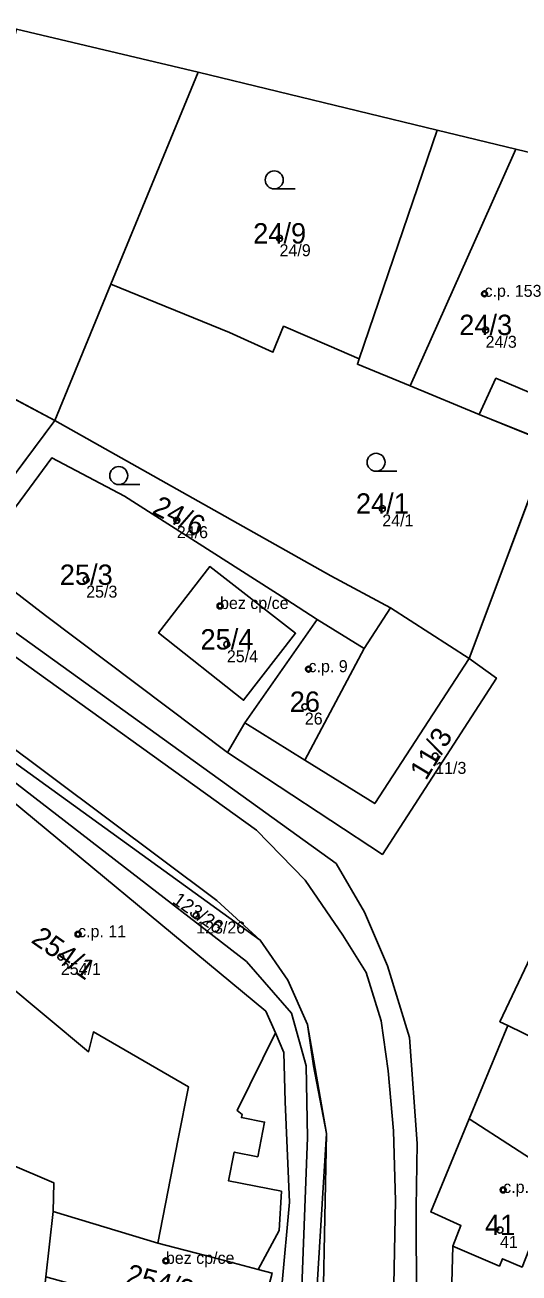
# Model space of a CAD drawing. Extents: x -603967 to -594699, y -1179315 to -1165625.
# Drawn here: x -597461.9 to -597420.7, y -1172597.8 to -1172493.5 of the extents above; entities that cross this region are included whole.
import ezdxf

# ---------------------------------------------------------------- set-up
doc = ezdxf.new("R2010")
doc.units = 0
for name, color, linetype in [('Definiční body', 7, 'Continuous'), ('Hranice parcel', 7, 'Continuous'), ('Parcelní čísla', 7, 'Continuous'), ('Polygon budovy', 7, 'Continuous'), ('Polygon parcely', 7, 'Continuous'), ('Vnitřní kresba', 7, 'Continuous'), ('Značky budov', 7, 'Continuous'), ('Značky kultur', 7, 'Continuous')]:
    doc.layers.add(name, color=color, linetype=linetype)

msp = doc.modelspace()

# ---------------------------------------------------------------- linework, layer by layer
at = {"layer": 'Definiční body'}
for centre in [(-597440.66, -1172511.29994), (-597423.54, -1172515.92994), (-597423.45, -1172518.94994), (-597432.08, -1172533.87994), (-597449.24, -1172534.85994), (-597456.81, -1172539.82994), (-597445.63, -1172542.01994), (-597445.06, -1172545.22994), (-597438.24, -1172547.29994), (-597438.55, -1172550.43994), (-597427.66, -1172554.55994), (-597447.62, -1172567.89994), (-597457.49, -1172569.44994), (-597458.93, -1172571.35994), (-597421.98, -1172590.81994), (-597422.25, -1172594.16994), (-597450.15, -1172596.74994)]:
    msp.add_circle(centre, 0.25, dxfattribs=at)
at = {"layer": 'Hranice parcel'}
for p, q in [((-597462.64, -1172493.8), (-597447.46, -1172497.41)), ((-597454.74, -1172515.13), (-597447.46, -1172497.41)), ((-597447.46, -1172497.41), (-597427.5, -1172502.26)), ((-597427.5, -1172502.26), (-597434.01, -1172521.36)), ((-597459.42, -1172526.51), (-597480.25, -1172515.46)), ((-597454.74, -1172515.13), (-597459.42, -1172526.51)), ((-597423.99, -1172526.01), (-597429.76, -1172523.62)), ((-597418.08, -1172528.4), (-597423.99, -1172526.01)), ((-597467.38, -1172537.18), (-597459.42, -1172526.51)), ((-597418.08, -1172528.4), (-597424.82, -1172546.4)), ((-597431.39, -1172542.18), (-597424.82, -1172546.4)), ((-597437.51, -1172543.14), (-597443.55, -1172551.79)), ((-597443.55, -1172551.79), (-597445.01, -1172554.25)), ((-597424.81, -1172584.87), (-597421.59, -1172577.08)), ((-597460.17, -1172598.07), (-597459.57, -1172592.62))]:
    msp.add_line(p, q, dxfattribs=at)
for points in [[(-597528.05, -1172498.17), (-597518.4, -1172504.13), (-597435.94, -1172563.53), (-597433.57, -1172567.6), (-597431.64, -1172572.1), (-597429.8, -1172578.09), (-597429.17, -1172586.93), (-597429.24, -1172592.29), (-597429.03, -1172657.03)], [(-597427.5, -1172502.26), (-597420.93, -1172503.84), (-597418.29, -1172504.48), (-597418.2, -1172505.62), (-597411.97, -1172507.07), (-597410.25, -1172507.47)], [(-597434.01, -1172521.36), (-597436.52, -1172520.28), (-597440.33, -1172518.64), (-597441.21, -1172520.81), (-597444.84, -1172519.15), (-597454.74, -1172515.13)], [(-597429.76, -1172523.62), (-597434.16, -1172521.81), (-597434.01, -1172521.36)], [(-597459.42, -1172526.51), (-597436.37, -1172539.5), (-597431.39, -1172542.18)], [(-597466.09, -1172538.29), (-597459.67, -1172529.63), (-597453.61, -1172532.84), (-597440.13, -1172541.45), (-597437.51, -1172543.14)], [(-597495.52, -1172531.46), (-597442.28, -1172569.94), (-597439.98, -1172573.3), (-597438.33, -1172576.99), (-597436.73, -1172586.11), (-597440.82, -1172652.61)], [(-597440.82, -1172652.61), (-597438.34, -1172586.43), (-597438.45, -1172580.46), (-597439.65, -1172576.06), (-597443.41, -1172571.74), (-597495.52, -1172531.46)], [(-597445.01, -1172554.25), (-597460.2, -1172542.81), (-597466.09, -1172538.29)], [(-597439.32, -1172544.3), (-597443.66, -1172549.9), (-597450.77, -1172544.27), (-597446.49, -1172538.73), (-597439.32, -1172544.3)], [(-597431.39, -1172542.18), (-597433.6, -1172545.57), (-597437.51, -1172543.14)], [(-597424.82, -1172546.4), (-597422.55, -1172548.04), (-597432.07, -1172562.78), (-597445.01, -1172554.25)], [(-597424.82, -1172546.4), (-597432.71, -1172558.53), (-597438.56, -1172554.9), (-597443.55, -1172551.79)], [(-597466.04, -1172555.82), (-597441.8, -1172575.89), (-597441.01, -1172577.69), (-597440.3, -1172579.33), (-597440.2, -1172583.46), (-597439.84, -1172591.85), (-597440.47, -1172598.85), (-597441.4, -1172612.41)], [(-597421.59, -1172577.08), (-597422.26, -1172576.76), (-597418.4, -1172568.61)], [(-597421.59, -1172577.08), (-597415.23, -1172580.2), (-597406.14, -1172584.66), (-597403.06, -1172585.98)], [(-597459.57, -1172592.62), (-597459.5, -1172590.23), (-597471.27, -1172585.2), (-597477.85, -1172582.21), (-597477.75, -1172581.98)], [(-597426.39, -1172602.61), (-597426.19, -1172595.53), (-597425.51, -1172593.78), (-597428.03, -1172592.65), (-597424.81, -1172584.87)], [(-597424.81, -1172584.87), (-597417.43, -1172589.67), (-597409.1, -1172592.88)], [(-597459.57, -1172592.62), (-597450.82, -1172595.27), (-597446.2, -1172596.48), (-597442.45, -1172597.46), (-597441.27, -1172597.77), (-597442.65, -1172602.95), (-597446.75, -1172601.81)]]:
    msp.add_lwpolyline(points, dxfattribs=at)
at = {"layer": 'Polygon budovy'}
for points in [[(-597423.8, -1172510.28), (-597429.76, -1172523.62), (-597423.99, -1172526.01), (-597422.59, -1172522.98), (-597418.73, -1172524.62), (-597414.3, -1172514.46), (-597415.05, -1172514.13), (-597411.97, -1172507.07), (-597418.2, -1172505.62), (-597418.29, -1172504.48), (-597420.93, -1172503.84)], [(-597486.02, -1172522.96), (-597467.38, -1172537.18), (-597459.42, -1172526.51), (-597480.25, -1172515.46)], [(-597446.49, -1172538.73), (-597450.77, -1172544.27), (-597443.66, -1172549.9), (-597439.32, -1172544.3)], [(-597443.55, -1172551.79), (-597438.56, -1172554.9), (-597433.6, -1172545.57), (-597437.51, -1172543.14)], [(-597422.26, -1172576.76), (-597421.59, -1172577.08), (-597415.23, -1172580.2), (-597413.06, -1172575.4), (-597403, -1172579.74), (-597402.94, -1172579.58), (-597399.56, -1172581.07), (-597397.55, -1172578.25), (-597401.34, -1172576.5), (-597411.7, -1172571.55), (-597418.4, -1172568.61)], [(-597403.06, -1172585.98), (-597406.14, -1172584.66), (-597415.23, -1172580.2), (-597421.59, -1172577.08), (-597424.81, -1172584.87), (-597417.43, -1172589.67), (-597416.34, -1172586.92), (-597408.17, -1172590.65), (-597408.35, -1172591.04), (-597407.37, -1172591.49), (-597407.03, -1172590.74), (-597406.53, -1172590.97), (-597404.86, -1172587.32), (-597403.82, -1172587.79)], [(-597428.03, -1172592.65), (-597425.51, -1172593.78), (-597426.19, -1172595.53), (-597422.3, -1172597.19), (-597422.03, -1172596.57), (-597420.41, -1172597.27), (-597417.43, -1172589.67), (-597424.81, -1172584.87)], [(-597460.17, -1172598.07), (-597446.75, -1172601.81), (-597442.65, -1172602.95), (-597441.27, -1172597.77), (-597442.45, -1172597.46), (-597446.2, -1172596.48), (-597450.82, -1172595.27), (-597459.57, -1172592.62)]]:
    msp.add_lwpolyline(points, close=True, dxfattribs=at)
msp.add_lwpolyline([(-597463.68, -1172573.37), (-597456.61, -1172579.27), (-597456.2, -1172577.62), (-597448.27, -1172582.19), (-597449.12, -1172586.55), (-597450.82, -1172595.27), (-597446.2, -1172596.48), (-597442.45, -1172597.46), (-597440.7, -1172594.22), (-597440.5, -1172590.93), (-597444.92, -1172590.06), (-597444.44, -1172587.66), (-597442.48, -1172588.04), (-597441.91, -1172585.15), (-597443.84, -1172584.77), (-597443.79, -1172584.51), (-597444.21, -1172584.18), (-597441.01, -1172577.69), (-597441.8, -1172575.89), (-597466.04, -1172555.82)], dxfattribs=at)
at = {"layer": 'Polygon parcely'}
for points in [[(-597429.92, -1172665.33), (-597429.03, -1172657.03), (-597429.24, -1172592.29), (-597429.17, -1172586.93), (-597429.8, -1172578.09), (-597431.64, -1172572.1), (-597433.57, -1172567.6), (-597435.94, -1172563.53), (-597518.4, -1172504.13), (-597528.05, -1172498.17), (-597529.32, -1172493.99), (-597512.01, -1172395.8), (-597507.16, -1172367.89)], [(-597418.08, -1172528.4), (-597424.82, -1172546.4), (-597422.55, -1172548.04), (-597432.07, -1172562.78), (-597445.01, -1172554.25), (-597460.2, -1172542.81), (-597466.09, -1172538.29), (-597467.38, -1172537.18), (-597486.02, -1172522.96), (-597490.89, -1172519.38), (-597505.52, -1172508.34), (-597509.97, -1172505.92), (-597516.24, -1172503.23), (-597517.21, -1172502.81), (-597528.05, -1172498.17), (-597518.4, -1172504.13), (-597435.94, -1172563.53), (-597433.57, -1172567.6), (-597431.64, -1172572.1), (-597429.8, -1172578.09), (-597429.17, -1172586.93), (-597429.24, -1172592.29), (-597429.03, -1172657.03)], [(-597532.25, -1172503.88), (-597520.62, -1172513.32), (-597509.01, -1172523.4), (-597500.85, -1172530.35), (-597481.89, -1172547.09), (-597477.95, -1172549.3), (-597473.88, -1172551.53), (-597466.04, -1172555.82), (-597441.8, -1172575.89), (-597441.01, -1172577.69), (-597440.3, -1172579.33), (-597440.2, -1172583.46), (-597439.84, -1172591.85), (-597440.47, -1172598.85), (-597441.4, -1172612.41), (-597444.15, -1172652.28), (-597440.82, -1172652.61), (-597438.34, -1172586.43), (-597438.45, -1172580.46), (-597439.65, -1172576.06), (-597443.41, -1172571.74), (-597495.52, -1172531.46), (-597528.77, -1172505.76)], [(-597528.77, -1172505.76), (-597495.52, -1172531.46), (-597442.28, -1172569.94), (-597439.98, -1172573.3), (-597438.33, -1172576.99), (-597436.73, -1172586.11), (-597440.82, -1172652.61), (-597440.93, -1172655.49), (-597441.21, -1172665.3)], [(-597426.39, -1172602.61), (-597426.19, -1172595.53), (-597425.51, -1172593.78), (-597428.03, -1172592.65), (-597424.81, -1172584.87), (-597421.59, -1172577.08), (-597422.26, -1172576.76), (-597418.4, -1172568.61)]]:
    msp.add_lwpolyline(points, dxfattribs=at)
for points in [[(-597447.46, -1172497.41), (-597427.5, -1172502.26), (-597420.93, -1172503.84), (-597418.29, -1172504.48), (-597418.2, -1172505.62), (-597411.97, -1172507.07), (-597410.25, -1172507.47), (-597408.98, -1172507.8), (-597408.65, -1172507.01), (-597400.52, -1172485.2), (-597420.52, -1172482.15), (-597454.45, -1172476.98), (-597470.37, -1172474.54), (-597472.64, -1172490.37), (-597472.89, -1172491.36), (-597466.39, -1172492.92), (-597462.64, -1172493.8)], [(-597447.46, -1172497.41), (-597462.64, -1172493.8), (-597464.36, -1172500.36), (-597468.08, -1172499.46), (-597472.04, -1172498.55), (-597473.11, -1172503.48), (-597477.19, -1172502.57), (-597482.51, -1172517.86), (-597486.02, -1172522.96), (-597480.25, -1172515.46), (-597459.42, -1172526.51), (-597454.74, -1172515.13)], [(-597427.5, -1172502.26), (-597447.46, -1172497.41), (-597454.74, -1172515.13), (-597444.84, -1172519.15), (-597441.21, -1172520.81), (-597440.33, -1172518.64), (-597436.52, -1172520.28), (-597434.01, -1172521.36)], [(-597427.5, -1172502.26), (-597434.01, -1172521.36), (-597434.16, -1172521.81), (-597429.76, -1172523.62), (-597423.99, -1172526.01), (-597418.08, -1172528.4), (-597410.25, -1172507.47), (-597411.97, -1172507.07), (-597418.2, -1172505.62), (-597418.29, -1172504.48), (-597420.93, -1172503.84)], [(-597459.42, -1172526.51), (-597480.25, -1172515.46), (-597486.02, -1172522.96), (-597467.38, -1172537.18)], [(-597454.74, -1172515.13), (-597459.42, -1172526.51), (-597436.37, -1172539.5), (-597431.39, -1172542.18), (-597424.82, -1172546.4), (-597418.08, -1172528.4), (-597423.99, -1172526.01), (-597429.76, -1172523.62), (-597434.16, -1172521.81), (-597434.01, -1172521.36), (-597436.52, -1172520.28), (-597440.33, -1172518.64), (-597441.21, -1172520.81), (-597444.84, -1172519.15)], [(-597440.13, -1172541.45), (-597437.51, -1172543.14), (-597433.6, -1172545.57), (-597431.39, -1172542.18), (-597436.37, -1172539.5), (-597459.42, -1172526.51), (-597467.38, -1172537.18), (-597466.09, -1172538.29), (-597459.67, -1172529.63), (-597453.61, -1172532.84)], [(-597466.09, -1172538.29), (-597460.2, -1172542.81), (-597445.01, -1172554.25), (-597443.55, -1172551.79), (-597437.51, -1172543.14), (-597440.13, -1172541.45), (-597453.61, -1172532.84), (-597459.67, -1172529.63)], [(-597495.52, -1172531.46), (-597443.41, -1172571.74), (-597439.65, -1172576.06), (-597438.45, -1172580.46), (-597438.34, -1172586.43), (-597440.82, -1172652.61), (-597436.73, -1172586.11), (-597438.33, -1172576.99), (-597439.98, -1172573.3), (-597442.28, -1172569.94)], [(-597439.32, -1172544.3), (-597446.49, -1172538.73), (-597450.77, -1172544.27), (-597443.66, -1172549.9)], [(-597439.32, -1172544.3), (-597443.66, -1172549.9), (-597450.77, -1172544.27), (-597446.49, -1172538.73)], [(-597437.51, -1172543.14), (-597443.55, -1172551.79), (-597438.56, -1172554.9), (-597432.71, -1172558.53), (-597424.82, -1172546.4), (-597431.39, -1172542.18), (-597433.6, -1172545.57)], [(-597443.55, -1172551.79), (-597445.01, -1172554.25), (-597432.07, -1172562.78), (-597422.55, -1172548.04), (-597424.82, -1172546.4), (-597432.71, -1172558.53), (-597438.56, -1172554.9)], [(-597441.27, -1172597.77), (-597442.65, -1172602.95), (-597446.75, -1172601.81), (-597446.09, -1172609.08), (-597441.4, -1172612.41), (-597440.47, -1172598.85), (-597439.84, -1172591.85), (-597440.2, -1172583.46), (-597440.3, -1172579.33), (-597441.01, -1172577.69), (-597441.8, -1172575.89), (-597466.04, -1172555.82), (-597469.1, -1172564.5), (-597475.64, -1172577.53), (-597477.75, -1172581.98), (-597477.85, -1172582.21), (-597471.27, -1172585.2), (-597459.5, -1172590.23), (-597459.57, -1172592.62), (-597450.82, -1172595.27), (-597446.2, -1172596.48), (-597442.45, -1172597.46)], [(-597397.55, -1172578.25), (-597401.34, -1172576.5), (-597411.7, -1172571.55), (-597418.4, -1172568.61), (-597422.26, -1172576.76), (-597421.59, -1172577.08), (-597415.23, -1172580.2), (-597406.14, -1172584.66), (-597403.06, -1172585.98), (-597399.56, -1172581.07)], [(-597493.46, -1172568.87), (-597495.24, -1172572.96), (-597501.89, -1172569.57), (-597496.27, -1172582.09), (-597487.15, -1172599.91), (-597483.7, -1172612.09), (-597484.51, -1172631.8), (-597484.61, -1172633.77), (-597470.17, -1172634.48), (-597468.95, -1172626.48), (-597463.35, -1172626.75), (-597463.23, -1172625.41), (-597460.17, -1172598.07), (-597459.57, -1172592.62), (-597459.5, -1172590.23), (-597471.27, -1172585.2), (-597477.85, -1172582.21), (-597477.75, -1172581.98), (-597485.47, -1172578.76), (-597487.24, -1172576.43), (-597490.24, -1172573.31)], [(-597408.54, -1172593.09), (-597403.51, -1172594.53), (-597403.82, -1172587.79), (-597403.06, -1172585.98), (-597406.14, -1172584.66), (-597415.23, -1172580.2), (-597421.59, -1172577.08), (-597424.81, -1172584.87), (-597417.43, -1172589.67), (-597409.1, -1172592.88)], [(-597412.9, -1172602.8), (-597411.99, -1172602.78), (-597408.57, -1172602.69), (-597407.97, -1172602.77), (-597404.91, -1172596.01), (-597409.72, -1172594.41), (-597409.1, -1172592.88), (-597417.43, -1172589.67), (-597424.81, -1172584.87), (-597428.03, -1172592.65), (-597425.51, -1172593.78), (-597426.19, -1172595.53), (-597426.39, -1172602.61), (-597422.52, -1172602.67), (-597418.51, -1172602.73)], [(-597459.57, -1172592.62), (-597460.17, -1172598.07), (-597446.75, -1172601.81), (-597442.65, -1172602.95), (-597441.27, -1172597.77), (-597442.45, -1172597.46), (-597446.2, -1172596.48), (-597450.82, -1172595.27)]]:
    msp.add_lwpolyline(points, close=True, dxfattribs=at)
at = {"layer": 'Vnitřní kresba'}
for p, q in [((-597525.44, -1172501.23), (-597442.58, -1172560.76)), ((-597423.8, -1172510.28), (-597420.93, -1172503.84)), ((-597527.79, -1172505.43), (-597445.89, -1172566.62)), ((-597429.76, -1172523.62), (-597423.8, -1172510.28)), ((-597422.59, -1172522.98), (-597423.99, -1172526.01)), ((-597418.73, -1172524.62), (-597422.59, -1172522.98)), ((-597438.56, -1172554.9), (-597433.6, -1172545.57)), ((-597442.58, -1172560.76), (-597438.52, -1172564.92)), ((-597438.52, -1172564.92), (-597435.37, -1172569.52)), ((-597445.89, -1172566.62), (-597442.28, -1172569.94)), ((-597435.37, -1172569.52), (-597433.42, -1172572.66)), ((-597433.42, -1172572.66), (-597432.17, -1172576.69)), ((-597463.68, -1172573.37), (-597456.61, -1172579.27)), ((-597438.33, -1172576.99), (-597437.82, -1172580.44)), ((-597432.17, -1172576.69), (-597431.58, -1172580.88)), ((-597456.61, -1172579.27), (-597456.2, -1172577.62)), ((-597456.2, -1172577.62), (-597448.27, -1172582.19)), ((-597444.21, -1172584.18), (-597441.01, -1172577.69)), ((-597437.82, -1172580.44), (-597436.73, -1172586.11)), ((-597431.58, -1172580.88), (-597431.15, -1172585.88)), ((-597448.27, -1172582.19), (-597449.12, -1172586.55)), ((-597443.79, -1172584.51), (-597444.21, -1172584.18)), ((-597443.79, -1172584.51), (-597443.84, -1172584.77)), ((-597443.84, -1172584.77), (-597441.91, -1172585.15)), ((-597441.91, -1172585.15), (-597442.48, -1172588.04)), ((-597449.12, -1172586.55), (-597450.82, -1172595.27)), ((-597438.15, -1172655.85), (-597436.73, -1172586.11)), ((-597431.15, -1172585.88), (-597430.97, -1172591.72)), ((-597444.44, -1172587.66), (-597444.92, -1172590.06)), ((-597442.48, -1172588.04), (-597444.44, -1172587.66)), ((-597444.92, -1172590.06), (-597440.5, -1172590.93)), ((-597440.5, -1172590.93), (-597440.7, -1172594.22)), ((-597430.97, -1172591.72), (-597432.3, -1172656.61)), ((-597442.45, -1172597.46), (-597440.7, -1172594.22)), ((-597426.19, -1172595.53), (-597422.3, -1172597.19)), ((-597422.3, -1172597.19), (-597422.03, -1172596.57)), ((-597422.03, -1172596.57), (-597420.41, -1172597.27))]:
    msp.add_line(p, q, dxfattribs=at)
at = {"layer": 'Značky budov'}
for centre in [(-597423.5468, -1172515.92916), (-597445.6368, -1172542.01916), (-597438.2468, -1172547.29916), (-597457.4968, -1172569.44916), (-597421.9868, -1172590.81916), (-597450.1568, -1172596.74916)]:
    msp.add_circle(centre, 0.175, dxfattribs=at)
at = {"layer": 'Značky kultur'}
for p, q in [((-597441.103, -1172507.16), (-597439.353, -1172507.16)), ((-597432.603, -1172530.76), (-597430.853, -1172530.76)), ((-597454.093, -1172531.87), (-597452.343, -1172531.87))]:
    msp.add_line(p, q, dxfattribs=at)
for centre in [(-597441.10286, -1172506.40981), (-597432.60286, -1172530.00981), (-597454.09286, -1172531.11981)]:
    msp.add_circle(centre, 0.75, dxfattribs=at)

# ---------------------------------------------------------------- texts
at = {"layer": 'Definiční body'}
for s, p in [('24/9', (-597440.66, -1172512.789)), ('c.p. 153', (-597423.54, -1172516.18)), ('24/3', (-597423.45, -1172520.439)), ('24/1', (-597432.08, -1172535.369)), ('24/6', (-597449.24, -1172536.349)), ('25/3', (-597456.81, -1172541.319)), ('bez cp/ce', (-597445.63, -1172542.27)), ('25/4', (-597445.06, -1172546.719)), ('c.p. 9', (-597438.24, -1172547.55)), ('26', (-597438.55, -1172551.929)), ('11/3', (-597427.66, -1172556.049)), ('c.p. 11', (-597457.49, -1172569.7)), ('123/26', (-597447.62, -1172569.389)), ('254/1', (-597458.93, -1172572.849)), ('c.p. 28', (-597421.98, -1172591.07)), ('41', (-597422.25, -1172595.659)), ('bez cp/ce', (-597450.15, -1172597))]:
    msp.add_text(s, height=0.999996, dxfattribs=at).set_placement(p)
at = {"layer": 'Parcelní čísla'}
for s, p in [('24/9', (-597442.865, -1172511.725)), ('24/3', (-597425.655, -1172519.375)), ('24/1', (-597434.285, -1172534.305)), ('25/3', (-597459.015, -1172540.255)), ('25/4', (-597447.265, -1172545.655)), ('26', (-597439.81, -1172550.865)), ('41', (-597423.51, -1172594.595))]:
    msp.add_text(s, height=1.699998, dxfattribs=at).set_placement(p)
for s, height, rotation, p in [('24/6', 1.699998, 333, (-597451.398, -1172534.237)), ('11/3', 1.699998, 59, (-597428.431, -1172556.669)), ('123/26', 1.14, 325, (-597449.687, -1172566.8)), ('254/1', 1.699998, 325, (-597461.496, -1172570.081)), ('254/2', 1.699998, 345, (-597453.589, -1172598.616))]:
    msp.add_text(s, height=height, rotation=rotation, dxfattribs=at).set_placement(p)

doc.saveas('drawing.dxf')
